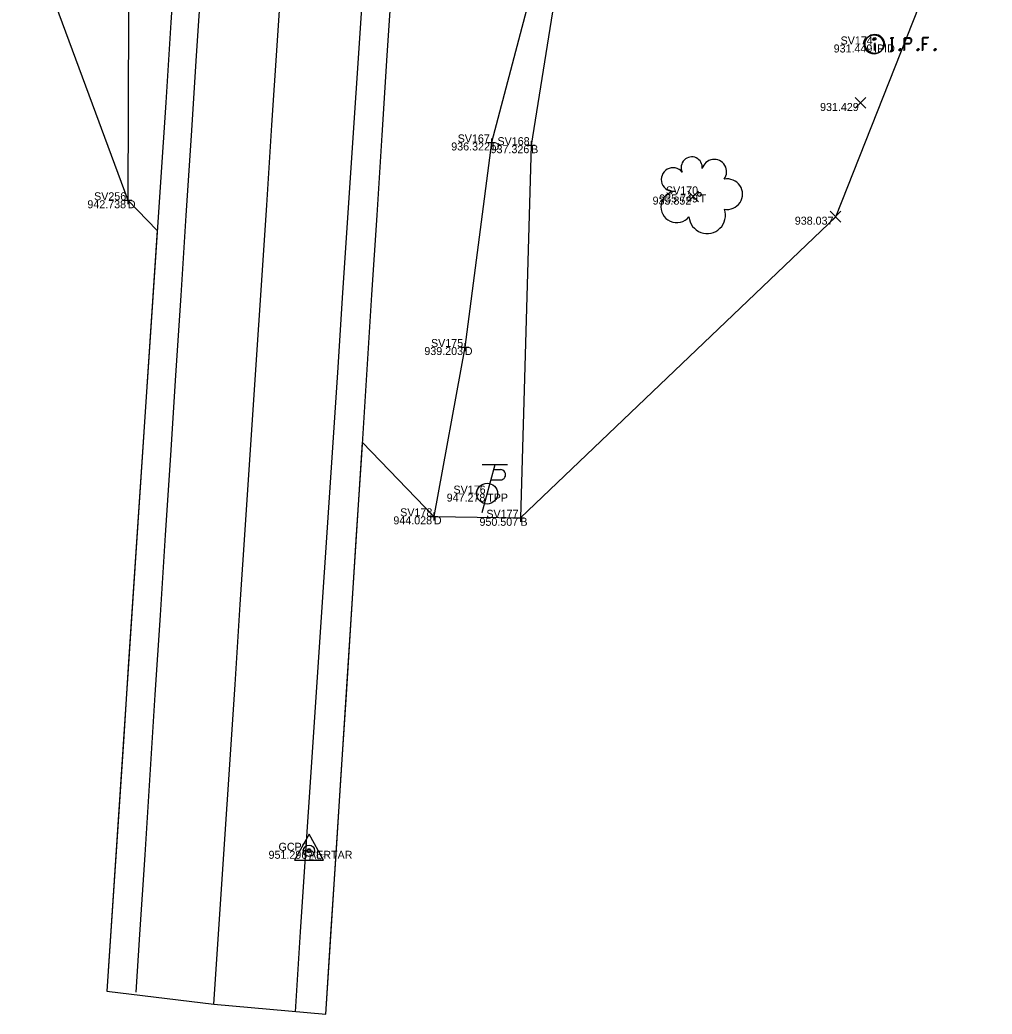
# Model space of a CAD drawing. Extents: x 1988835 to 1989144, y 657973 to 659339.
# Drawn here: x 1988953.7 to 1989075.2, y 658491.9 to 658616.1 of the extents above; entities that cross this region are included whole.
import ezdxf

# ---------------------------------------------------------------- set-up
doc = ezdxf.new("R2010")
doc.units = 0
for name, color, linetype in [('DR_X_Ditch', 7, 'Continuous'), ('DT_X_Terrain_Boundary', 7, 'Continuous'), ('PM_X_CL_Pass_Proh_Rt', 7, 'Continuous'), ('PV_X_EOP', 7, 'Continuous'), ('PV_X_Shoulder_Aggregate', 7, 'Continuous'), ('SV_X_Break_Lines', 7, 'Continuous'), ('SV_X_Mon_Cells_Found', 7, 'Continuous'), ('SV_X_Random_Point', 7, 'Continuous'), ('SV_X_Shot_Marker', 7, 'Continuous'), ('SV_X_Text_Comment', 7, 'Continuous'), ('SV_X_Text_Elevation', 7, 'Continuous'), ('UT_X_Misc_Cells', 7, 'Continuous'), ('UT_X_Telecom', 7, 'Continuous'), ('UT_X_Telecom_Cells', 7, 'Continuous'), ('VG_X_Cells', 7, 'Continuous')]:
    doc.layers.add(name, color=color, linetype=linetype)

msp = doc.modelspace()

# ---------------------------------------------------------------- linework, layer by layer
at = {"layer": 'DR_X_Ditch'}
for points in [[(1989023.79, 658642.94), (1989012.7, 658600.75), (1989009.34, 658575.2), (1989005.48, 658554.05)], [(1988967.37, 658640.15), (1988967.38, 658628.69), (1988967.24, 658593.53)]]:
    msp.add_lwpolyline(points, dxfattribs=at)
at = {"layer": 'DT_X_Terrain_Boundary'}
for points in [[(1988964.62, 658494.73), (1988978, 658493.13), (1988991.98, 658491.88), (1988996.56, 658563.26), (1989005.48, 658554.05), (1989016.29, 658553.87), (1989055.69, 658591.48), (1989072.05, 658632.76), (1989075.24, 658671.01), (1989070.71, 658691.89), (1989069.57, 658706.91), (1989055.31, 658717.34), (1989045.38, 658731.75), (1989037.8, 658764.08), (1989044.5, 658795.25), (1989034.59, 658795.83), (1989024.05, 658796.33), (1989020.1, 658798.63), (1989011.65, 658798.86), (1989014.02, 658836.36)], [(1988953.75, 658630), (1988967.24, 658593.53), (1988970.91, 658589.74), (1988964.62, 658494.73)]]:
    msp.add_lwpolyline(points, dxfattribs=at)
at = {"layer": 'PM_X_CL_Pass_Proh_Rt'}
msp.add_lwpolyline([(1988978, 658493.13), (1988978.66, 658503.11), (1988979.32, 658513.09), (1988979.98, 658523.07), (1988980.64, 658533.04), (1988981.29, 658543.02), (1988981.95, 658553), (1988982.61, 658562.98), (1988983.27, 658572.96), (1988983.93, 658582.93), (1988984.59, 658592.91), (1988985.25, 658602.89), (1988985.91, 658612.87), (1988986.57, 658622.85)], dxfattribs=at)
at = {"layer": 'PV_X_EOP'}
for points in [[(1988976.44, 658621.56), (1988975.79, 658611.58), (1988975.15, 658601.6), (1988974.5, 658591.62), (1988973.86, 658581.64), (1988973.21, 658571.66), (1988972.57, 658561.68), (1988971.92, 658551.7), (1988971.28, 658541.72), (1988970.63, 658531.74), (1988969.98, 658521.76), (1988969.34, 658511.79), (1988968.69, 658501.81), (1988968.23, 658494.64)], [(1988988.17, 658492.18), (1988988.83, 658502.16), (1988989.49, 658512.13), (1988990.16, 658522.11), (1988990.82, 658532.09), (1988991.48, 658542.07), (1988992.14, 658552.05), (1988992.8, 658562.02), (1988993.46, 658572), (1988994.12, 658581.98), (1988994.78, 658591.96), (1988995.44, 658601.94), (1988996.1, 658611.92), (1988996.76, 658621.89)]]:
    msp.add_lwpolyline(points, dxfattribs=at)
at = {"layer": 'PV_X_Shoulder_Aggregate'}
for points in [[(1988973.29, 658625.71), (1988972.63, 658615.73), (1988971.97, 658605.75), (1988971.31, 658595.77), (1988970.65, 658585.79), (1988969.99, 658575.82), (1988969.32, 658565.84), (1988968.66, 658555.86), (1988968, 658545.88), (1988967.34, 658535.9), (1988966.68, 658525.93), (1988966.02, 658515.95), (1988965.36, 658505.97), (1988964.7, 658495.99), (1988964.62, 658494.73)], [(1988991.98, 658491.88), (1988992.62, 658501.86), (1988993.26, 658511.84), (1988993.9, 658521.82), (1988994.54, 658531.8), (1988995.18, 658541.78), (1988995.82, 658551.76), (1988996.46, 658561.74), (1988997.1, 658571.72), (1988997.74, 658581.7), (1988998.38, 658591.67), (1988999.01, 658601.65), (1988999.65, 658611.63), (1989000.29, 658621.61)]]:
    msp.add_lwpolyline(points, dxfattribs=at)
at = {"layer": 'SV_X_Break_Lines'}
msp.add_lwpolyline([(1989020.62, 658619.19), (1989017.63, 658600.41), (1989016.29, 658553.87)], dxfattribs=at)
at = {"layer": 'SV_X_Mon_Cells_Found'}
for p, q in [((1989060.48, 658613.11), (1989060.48, 658612.23)), ((1989060.57, 658613.19), (1989060.57, 658612.3))]:
    msp.add_line(p, q, dxfattribs=at)
for points in [[(1989062.51, 658613.79), (1989062.86, 658613.79)], [(1989062.6, 658613.87), (1989062.95, 658613.87)], [(1989062.69, 658612.19), (1989062.69, 658613.79)], [(1989062.78, 658612.27), (1989062.78, 658613.87)], [(1989064.25, 658612.19), (1989064.25, 658613.79), (1989064.78, 658613.79), (1989064.84, 658613.78), (1989064.91, 658613.75), (1989064.95, 658613.73), (1989064.98, 658613.7), (1989065.02, 658613.64), (1989065.06, 658613.58), (1989065.08, 658613.48), (1989065.08, 658613.33), (1989065.07, 658613.28), (1989065.05, 658613.2), (1989065, 658613.11), (1989064.96, 658613.07), (1989064.93, 658613.05), (1989064.87, 658613.02), (1989064.78, 658613.01), (1989064.25, 658613.01)], [(1989064.34, 658612.27), (1989064.34, 658613.87), (1989064.87, 658613.87), (1989064.93, 658613.86), (1989065, 658613.83), (1989065.04, 658613.81), (1989065.07, 658613.78), (1989065.11, 658613.72), (1989065.15, 658613.66), (1989065.17, 658613.56), (1989065.17, 658613.4), (1989065.16, 658613.35), (1989065.14, 658613.28), (1989065.09, 658613.19), (1989065.05, 658613.15), (1989065.02, 658613.13), (1989064.96, 658613.1), (1989064.87, 658613.09), (1989064.34, 658613.09)], [(1989067.26, 658613.79), (1989066.5, 658613.79), (1989066.5, 658612.19)], [(1989067.35, 658613.87), (1989066.59, 658613.87), (1989066.59, 658612.27)], [(1989063.74, 658612.48), (1989063.79, 658612.48), (1989063.82, 658612.46), (1989063.86, 658612.41), (1989063.86, 658612.35), (1989063.82, 658612.3), (1989063.79, 658612.27), (1989063.74, 658612.27), (1989063.7, 658612.3), (1989063.67, 658612.35), (1989063.67, 658612.41), (1989063.7, 658612.46), (1989063.74, 658612.48)], [(1989065.99, 658612.48), (1989066.04, 658612.48), (1989066.07, 658612.46), (1989066.11, 658612.41), (1989066.11, 658612.35), (1989066.07, 658612.3), (1989066.04, 658612.27), (1989065.99, 658612.27), (1989065.95, 658612.3), (1989065.92, 658612.35), (1989065.92, 658612.41), (1989065.95, 658612.46), (1989065.99, 658612.48)], [(1989066.5, 658613.01), (1989067.04, 658613.01)], [(1989066.59, 658613.09), (1989067.13, 658613.09)], [(1989068.13, 658612.48), (1989068.19, 658612.48), (1989068.22, 658612.46), (1989068.26, 658612.41), (1989068.26, 658612.35), (1989068.22, 658612.3), (1989068.19, 658612.27), (1989068.13, 658612.27), (1989068.1, 658612.3), (1989068.07, 658612.35), (1989068.07, 658612.41), (1989068.1, 658612.46), (1989068.13, 658612.48)], [(1989062.51, 658612.19), (1989062.86, 658612.19)], [(1989062.6, 658612.27), (1989062.95, 658612.27)], [(1989063.65, 658612.41), (1989063.7, 658612.41), (1989063.73, 658612.38), (1989063.77, 658612.33), (1989063.77, 658612.27), (1989063.73, 658612.22), (1989063.7, 658612.19), (1989063.65, 658612.19), (1989063.61, 658612.22), (1989063.58, 658612.27), (1989063.58, 658612.33), (1989063.61, 658612.38), (1989063.65, 658612.41)], [(1989065.9, 658612.41), (1989065.95, 658612.41), (1989065.98, 658612.38), (1989066.02, 658612.33), (1989066.02, 658612.27), (1989065.98, 658612.22), (1989065.95, 658612.19), (1989065.9, 658612.19), (1989065.86, 658612.22), (1989065.83, 658612.27), (1989065.83, 658612.33), (1989065.86, 658612.38), (1989065.9, 658612.41)], [(1989068.04, 658612.41), (1989068.1, 658612.41), (1989068.13, 658612.38), (1989068.17, 658612.33), (1989068.17, 658612.27), (1989068.13, 658612.22), (1989068.1, 658612.19), (1989068.04, 658612.19), (1989068.01, 658612.22), (1989067.98, 658612.27), (1989067.98, 658612.33), (1989068.01, 658612.38), (1989068.04, 658612.41)]]:
    msp.add_lwpolyline(points, dxfattribs=at)
for centre, radius in [((1989060.48, 658612.99), 1.2), ((1989060.57, 658613.07), 1.2), ((1989060.48, 658613.64), 0.16), ((1989060.57, 658613.72), 0.16)]:
    msp.add_circle(centre, radius, dxfattribs=at)
at = {"layer": 'SV_X_Random_Point'}
for p, q in [((1989058.12, 658605.02), (1989059.45, 658606.35)), ((1989058.12, 658606.35), (1989059.45, 658605.02)), ((1989037.2, 658593.32), (1989038.54, 658594.66)), ((1989037.2, 658594.66), (1989038.54, 658593.32)), ((1989055.02, 658590.81), (1989056.35, 658592.15)), ((1989055.02, 658592.15), (1989056.35, 658590.81))]:
    msp.add_line(p, q, dxfattribs=at)
at = {"layer": 'SV_X_Shot_Marker'}
for p, q in [((1989012.2, 658600.75), (1989013.2, 658600.75)), ((1989012.7, 658601.25), (1989012.7, 658600.25)), ((1989012.7, 658600.75), (1989012.7, 658600.75)), ((1989017.13, 658600.41), (1989018.13, 658600.41)), ((1989017.63, 658600.91), (1989017.63, 658599.91)), ((1989017.63, 658600.41), (1989017.63, 658600.41)), ((1988967.24, 658594.03), (1988967.24, 658593.03)), ((1988966.74, 658593.53), (1988967.74, 658593.53)), ((1988967.24, 658593.53), (1988967.24, 658593.53)), ((1989009.34, 658575.7), (1989009.34, 658574.7)), ((1989008.84, 658575.2), (1989009.84, 658575.2)), ((1989009.34, 658575.2), (1989009.34, 658575.2)), ((1989005.48, 658554.55), (1989005.48, 658553.55)), ((1989016.29, 658554.37), (1989016.29, 658553.37)), ((1989004.98, 658554.05), (1989005.98, 658554.05)), ((1989005.48, 658554.05), (1989005.48, 658554.05)), ((1989015.79, 658553.87), (1989016.79, 658553.87)), ((1989016.29, 658553.87), (1989016.29, 658553.87))]:
    msp.add_line(p, q, dxfattribs=at)
at = {"layer": 'SV_X_Text_Elevation'}
msp.add_line((1988989.88, 658512.28), (1988989.88, 658512.28), dxfattribs=at)
msp.add_lwpolyline([(1988988.08, 658511.12), (1988991.68, 658511.12), (1988989.88, 658514.34)], close=True, dxfattribs=at)
for radius in [0.7, 0.16]:
    msp.add_circle((1988989.88, 658512.28), radius, dxfattribs=at)
at = {"layer": 'UT_X_Misc_Cells'}
for p, q in [((1989013.1, 658560.49), (1989011.49, 658554.49)), ((1989014.7, 658560.49), (1989011.5, 658560.49)), ((1989012.94, 658559.89), (1989013.79, 658559.89)), ((1989012.6, 658558.61), (1989013.79, 658558.61))]:
    msp.add_line(p, q, dxfattribs=at)
msp.add_circle((1989012.14, 658556.89), 1.3, dxfattribs=at)
msp.add_arc((1989013.8, 658559.25), 0.638, 268.8767, 91.1233, dxfattribs=at)
at = {"layer": 'UT_X_Telecom'}
msp.add_line((1988989.88, 658512.28), (1988989.88, 658512.28), dxfattribs=at)
msp.add_circle((1988989.88, 658512.28), 0.25, dxfattribs=at)
at = {"layer": 'VG_X_Cells'}
msp.add_circle((1989038.68, 658594.26), 0.24, dxfattribs=at)
for centre, radius, start, end in [((1989037.7, 658597.63), 1.32, 354.0047, 205.9741), ((1989035.37, 658596.12), 1.47, 39.0625, 279.5412), ((1989040.51, 658597.09), 1.55, 323.83, 165.0376), ((1989042.14, 658594.29), 1.91, 259.1453, 101.4596), ((1989035.83, 658592.71), 1.97, 96.1722, 320.5737), ((1989039.63, 658591.65), 2.28, 184.9476, 19.4572)]:
    msp.add_arc(centre, radius, start, end, dxfattribs=at)

# ---------------------------------------------------------------- texts
at = {"layer": 'SV_X_Text_Comment'}
for s, p in [('SV174', (1989056.3, 658612.99)), ('SV167', (1989008.45, 658600.75)), ('SV168', (1989013.43, 658600.41)), ('SV170', (1989034.48, 658594.26)), ('SV256', (1988963.02, 658593.53)), ('SV175', (1989005.12, 658575.2)), ('SV176', (1989007.93, 658556.89)), ('SV178', (1989001.27, 658554.05)), ('SV177', (1989012.04, 658553.87)), ('GCP2', (1988986.07, 658512.28))]:
    msp.add_text(s, height=1, dxfattribs=at).set_placement(p)
at = {"layer": 'UT_X_Telecom'}
for s, height, p in [('IPID', 1, (1989060.48, 658611.99)), ('D', 1, (1989012.7, 658599.75)), ('B', 1, (1989017.63, 658599.41)), ('T', 1, (1989038.68, 658593.26)), ('D', 1, (1988967.24, 658592.53)), ('D', 1, (1989009.34, 658574.2)), ('TPP', 1, (1989012.14, 658555.89)), ('D', 1, (1989005.48, 658553.05)), ('B', 1, (1989016.29, 658552.87)), ('AERTAR', 1, (1988989.88, 658511.28)), ('Name: GCP2', 0.3, (1988989.88, 658511.58)), ('Index: 1', 0.3, (1988989.88, 658511.97)), ('ΔZ: 0.027', 0.3, (1988989.88, 658511.18))]:
    msp.add_text(s, height=height, dxfattribs=at).set_placement(p)
at = {"layer": 'UT_X_Telecom_Cells'}
for s, p in [('931.449', (1989055.44, 658611.99)), ('931.429', (1989053.74, 658604.68)), ('936.322', (1989007.65, 658599.75)), ('937.326', (1989012.57, 658599.41)), ('935.852', (1989032.81, 658592.99)), ('935.749', (1989033.64, 658593.26)), ('942.738', (1988962.18, 658592.53)), ('938.037', (1989050.58, 658590.48)), ('939.203', (1989004.29, 658574.2)), ('947.278', (1989007.08, 658555.89)), ('944.028', (1989000.42, 658553.05)), ('950.507', (1989011.18, 658552.87)), ('951.296', (1988984.82, 658511.28))]:
    msp.add_text(s, height=1, dxfattribs=at).set_placement(p)

doc.saveas('drawing.dxf')
